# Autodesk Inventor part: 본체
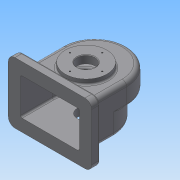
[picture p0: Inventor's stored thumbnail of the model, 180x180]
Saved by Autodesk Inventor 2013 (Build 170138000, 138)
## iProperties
Created: 2017-11
Part Number: 본체
Material: 일반
Document SubType Name: Modeling
Designer: Administrator
Density: 1 g/cm^3
Author: Administrator
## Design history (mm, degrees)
sketch "스케치1"
  geometry: L1 (-58, -65)-(-58, 15); L2 (58, 15)-(58, -65); L3 (58, -65)-(-58, -65); A1 r 58 centre (0, 15) between (58, 15) and (-58, 15); 1 further point
  constraints: 6 end point, 2 perpendicular, 2 point on circle, 1 centre point, 1 tangent, 1 vertical, 1 vertical alignment
  dimensions: "d0" = 116 distance of L2.end L1.start; "d2" = 58 radius of A1; "d3" = 80 vertical distance of L1.start A1.centre; "d5" = 65 vertical distance of point (0, 0) L1.start
extrude "돌출1" new body sketch "스케치1" distance "d6" = 38; taper "d7" = 0 deg
sketch "스케치2"
  geometry: L1 (58, -65)-(58, 15) reference; L2 (-58, 15)-(-58, -65) reference; L3 (-58, -65)-(58, -65) reference; A1 r 58 centre (0, -8) between (58, -8) and (-58, -8); 1 further point
  constraints: 2 point on circle, 2 point on line, 1 centre point
  dimensions: "d9" = 58 radius of A1; "d10" = 57 distance from line of L3 A1.centre
extrude "돌출2" join sketch "스케치2" distance "d11" = 38; taper "d12" = 0 deg
feature "쉘1" dims "d13" = 5
sketch "스케치3"
  geometry: C1 r 37.5 at (0, 0); 1 further point
  constraints: 1 centre point, 1 coincident
  dimensions: "d14" = 37.5 radius of C1
extrude "돌출3" join sketch "스케치3" distance "d15" = 9; taper "d16" = 0 deg
sketch "스케치4"
  geometry: C1 r 31 at (0, 0); 1 further point
  constraints: 2 coincident, 1 centre point
  dimensions: "d17" = 31 radius of C1
extrude "돌출4" join sketch "스케치4" distance "d18" = 10; taper "d19" = 0 deg
sketch "스케치5"
  geometry: L1 (5, -5)-(111, -5) reference; L2 (111, -5)-(111, -71) reference; L3 (111, -71)-(5, -71) reference; L4 (5, -71)-(5, -5) reference; L5 (116, 0)-(0, 0) reference; L6 (0, 0)-(0, -76) reference; L7 (116, -76)-(0, -76) reference; L8 (116, 0)-(116, -76) reference; L9 (133, 17)-(-17, 17); L10 (-17, 17)-(-17, -93); L11 (-17, -93)-(133, -93); L12 (133, -93)-(133, 17); L13 (133, 17)-(-17, -93); L14 (-17, 17)-(133, -93); L15 (0, -38)-(116, -38) reference; 4 further points
  constraints: 12 end point, 4 midpoint, 2 parallel, 1 horizontal, 1 perpendicular, 1 vertical alignment
  dimensions: "d20" = 150 distance of L11.end L10.end; "d21" = 110 distance of L10.end L9.end; "d22" = 55 distance from line of L9.start L15; "d25" = 75 horizontal distance of L9.start point (58, 0)
extrude "돌출5" join sketch "스케치5" distance "d26" = 15; taper "d27" = 0 deg
fillet "모깎기1" dims "d28" = 12
fillet "모깎기2" dims "d29" = 8
fillet "모깎기3" dims "d30" = 3
hole "구멍1" diameter "d33" = 32; stored, may be unused: countersink angle "d37" = 90 deg, drill point angle "d39" = 0 deg; dims "d31" = 10, "d32" = 10, "d34" = 6, "d35" = 4, "d36" = 2, "d38" = 123
chamfer "모따기1" distance "d40" = 1; stored, may be unused: second distance "d41" = 2, angle "d42" = 45 deg
sketch "스케치6"
  geometry: C1 r 37.5 at (0, 0) reference; 1 further point
  constraints: 1 vertical alignment
  dimensions: "d43" = 29 distance of C1.centre point (0, 29)
hole "구멍2" sketch "스케치6" at (0, 29) diameter "d44" = 2.459; stored, may be unused: countersink angle "d48" = 90 deg, drill point angle "d50" = 118 deg; dims "d45" = 6, "d46" = 4, "d47" = 2, "d49" = 8
sketch "스케치7"
  geometry: C1 r 31 at (0, 0) reference; 1 further point
  constraints: 1 vertical alignment
  dimensions: "d51" = 26 distance of point (0, 26) C1.centre
hole "구멍3" sketch "스케치7" at (0, 26) diameter "d52" = 2.459; stored, may be unused: countersink angle "d56" = 90 deg, drill point angle "d58" = 118 deg; dims "d53" = 6, "d54" = 4, "d55" = 2, "d57" = 8
node "작업 평면1"
sketch "스케치8"
  geometry: L1 (13, 93)-(113, 93) reference; C1 r 6 at (63, 74); 2 further points
  constraints: 1 centre point, 1 midpoint, 1 vertical alignment
  dimensions: "d63" = 6 radius of C1; "d64" = 19 distance from line of C1.centre L1
extrude "돌출6" join sketch "스케치8" stored distance "d65" = 15; taper "d66" = 0 deg
node "솔리드1"
pattern_circular "원형 패턴1" dims angle "d60" = 360 deg
other parameters: "d62" = -144
